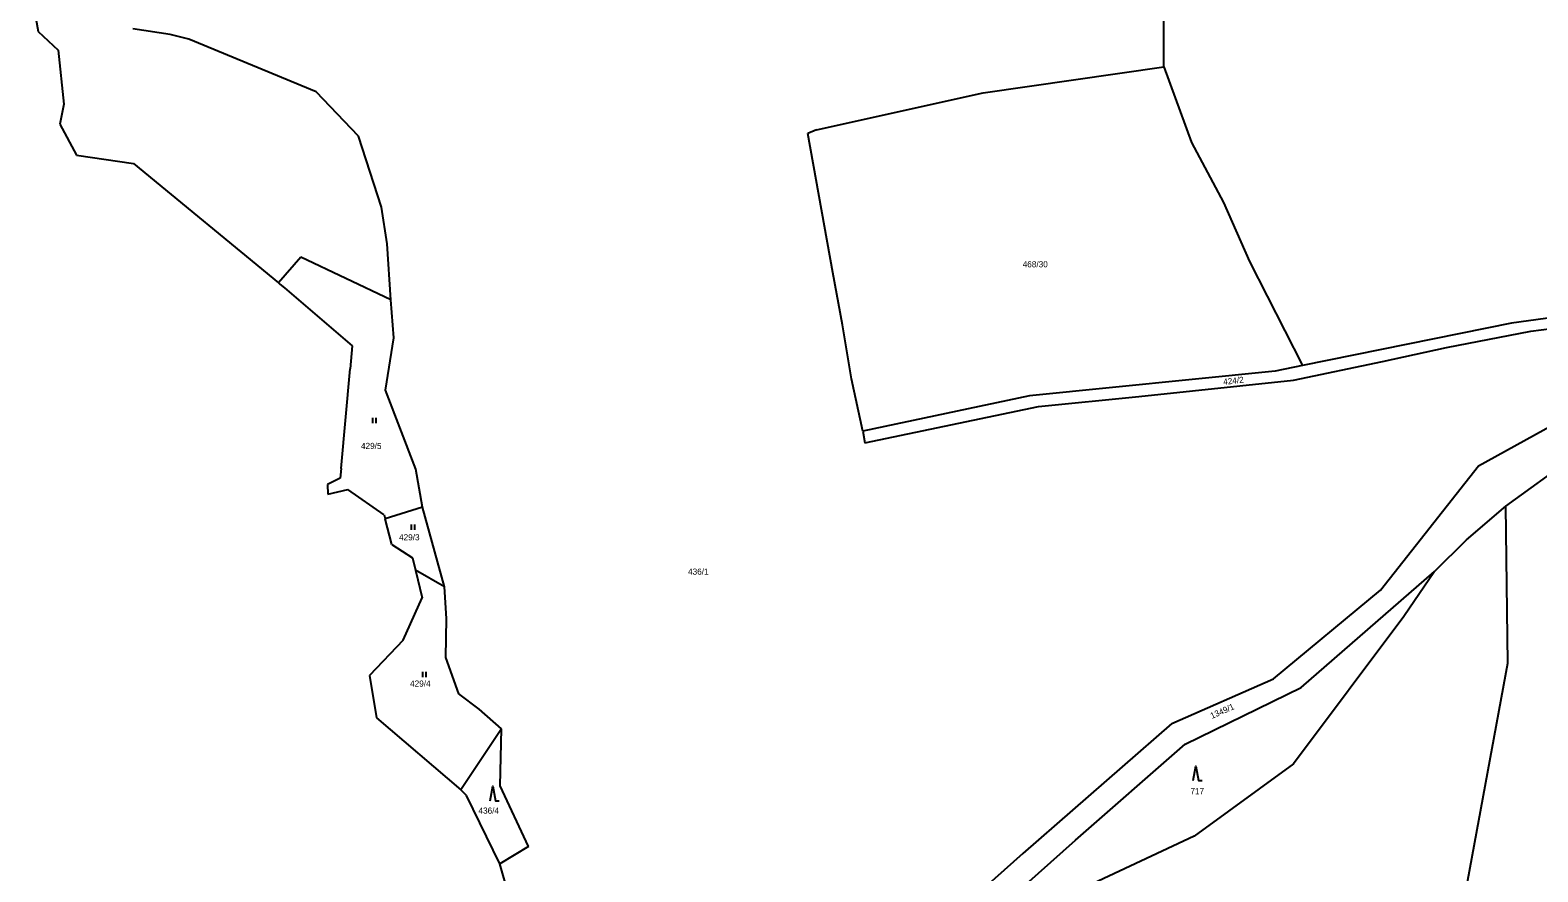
# Model space of a CAD drawing. Extents: x -852001 to -842497, y -1063614 to -1052182.
# Drawn here: x -845907.6 to -845490.2, y -1062182 to -1061949.1 of the extents above; entities that cross this region are included whole.
import ezdxf

# ---------------------------------------------------------------- set-up
doc = ezdxf.new("R2010")
doc.units = 0
for name, color, linetype in [('Default', 7, 'Continuous'), ('KN_HRANICE', 7, 'Continuous'), ('KN_KULTURY', 7, 'Continuous'), ('KN_PARCELY', 7, 'Continuous')]:
    doc.layers.add(name, color=color, linetype=linetype)

# ---------------------------------------------------------------- blocks, each defined once
blk = doc.blocks.new('306')
at = {"layer": 'Default'}
for p, q in [((-0.5, 1.5), (-0.5, 0)), ((0.5, 0), (0.5, 1.5))]:
    blk.add_line(p, q, dxfattribs=at)
blk = doc.blocks.new('308')
at = {"layer": 'Default'}
blk.add_lwpolyline([(-0.75, 0), (0, 4), (0.75, 0), (1.75, 0)], dxfattribs=at)

msp = doc.modelspace()

# ---------------------------------------------------------------- linework, layer by layer
at = {"layer": 'KN_HRANICE'}
for p, q in [((-845907.61, -1061936.84), (-845905.35, -1061949.46)), ((-845907.61, -1061936.84), (-845905.35, -1061949.46)), ((-845593.78, -1061959.19), (-845593.81, -1061940.64)), ((-845593.78, -1061959.19), (-845593.81, -1061940.64)), ((-845905.35, -1061949.46), (-845899.89, -1061954.64)), ((-845905.35, -1061949.46), (-845899.89, -1061954.64)), ((-845868.81, -1061950.29), (-845879.15, -1061948.69)), ((-845868.81, -1061950.29), (-845879.15, -1061948.69)), ((-845863.64, -1061951.61), (-845868.81, -1061950.29)), ((-845863.64, -1061951.61), (-845868.81, -1061950.29)), ((-845899.89, -1061954.64), (-845898.3, -1061969.58)), ((-845899.89, -1061954.64), (-845898.3, -1061969.58)), ((-845828.42, -1061966.16), (-845863.64, -1061951.61)), ((-845828.42, -1061966.16), (-845863.64, -1061951.61)), ((-845643.81, -1061966.46), (-845593.78, -1061959.19)), ((-845643.81, -1061966.46), (-845593.78, -1061959.19)), ((-845593.78, -1061959.19), (-845586.1, -1061980.16)), ((-845593.78, -1061959.19), (-845586.1, -1061980.16)), ((-845816.75, -1061978.37), (-845828.42, -1061966.16)), ((-845816.75, -1061978.37), (-845828.42, -1061966.16)), ((-845689.93, -1061976.66), (-845643.81, -1061966.46)), ((-845689.93, -1061976.66), (-845643.81, -1061966.46)), ((-845898.3, -1061969.58), (-845899.42, -1061975.13)), ((-845898.3, -1061969.58), (-845899.42, -1061975.13)), ((-845899.42, -1061975.13), (-845894.81, -1061983.7)), ((-845899.42, -1061975.13), (-845894.81, -1061983.7)), ((-845810.39, -1061998.09), (-845816.75, -1061978.37)), ((-845810.39, -1061998.09), (-845816.75, -1061978.37)), ((-845689.93, -1061976.66), (-845692.3, -1061977.63)), ((-845689.93, -1061976.66), (-845692.3, -1061977.63)), ((-845685.43, -1062016.18), (-845692.3, -1061977.63)), ((-845685.43, -1062016.18), (-845692.3, -1061977.63)), ((-845894.81, -1061983.7), (-845879, -1061985.97)), ((-845894.81, -1061983.7), (-845879, -1061985.97)), ((-845586.1, -1061980.16), (-845577.29, -1061996.8)), ((-845586.1, -1061980.16), (-845577.29, -1061996.8)), ((-845879, -1061985.97), (-845838.89, -1062019.01)), ((-845879, -1061985.97), (-845838.89, -1062019.01)), ((-845808.8, -1062008.17), (-845810.39, -1061998.09)), ((-845808.8, -1062008.17), (-845810.39, -1061998.09)), ((-845577.29, -1061996.8), (-845570.06, -1062013.09)), ((-845577.29, -1061996.8), (-845570.06, -1062013.09)), ((-845807.74, -1062023.68), (-845808.8, -1062008.17)), ((-845807.74, -1062023.68), (-845808.8, -1062008.17)), ((-845832.72, -1062011.87), (-845838.89, -1062019.01)), ((-845832.72, -1062011.87), (-845838.89, -1062019.01)), ((-845807.74, -1062023.68), (-845832.72, -1062011.87)), ((-845807.74, -1062023.68), (-845832.72, -1062011.87)), ((-845570.06, -1062013.09), (-845555.39, -1062041.89)), ((-845570.06, -1062013.09), (-845555.39, -1062041.89)), ((-845682.78, -1062030.58), (-845685.43, -1062016.18)), ((-845682.78, -1062030.58), (-845685.43, -1062016.18)), ((-845838.89, -1062019.01), (-845838.48, -1062019.35)), ((-845838.89, -1062019.01), (-845838.48, -1062019.35)), ((-845838.48, -1062019.35), (-845837.23, -1062020.38)), ((-845838.48, -1062019.35), (-845837.23, -1062020.38)), ((-845837.23, -1062020.38), (-845818.43, -1062036.47)), ((-845837.23, -1062020.38), (-845818.43, -1062036.47)), ((-845806.95, -1062034.24), (-845807.74, -1062023.68)), ((-845806.95, -1062034.24), (-845807.74, -1062023.68)), ((-845470.38, -1062026.35), (-845497.51, -1062030.16)), ((-845470.38, -1062026.35), (-845497.51, -1062030.16)), ((-845492.16, -1062032.41), (-845469.1, -1062029.34)), ((-845492.16, -1062032.41), (-845469.1, -1062029.34)), ((-845809.2, -1062048.66), (-845806.95, -1062034.24)), ((-845809.2, -1062048.66), (-845806.95, -1062034.24)), ((-845680.26, -1062045.53), (-845682.78, -1062030.58)), ((-845680.26, -1062045.53), (-845682.78, -1062030.58)), ((-845497.51, -1062030.16), (-845555.39, -1062041.89)), ((-845497.51, -1062030.16), (-845555.39, -1062041.89)), ((-845515.5, -1062036.89), (-845492.16, -1062032.41)), ((-845515.5, -1062036.89), (-845492.16, -1062032.41)), ((-845818.43, -1062036.47), (-845819.01, -1062042.76)), ((-845818.43, -1062036.47), (-845819.01, -1062042.76)), ((-845533.24, -1062040.8), (-845515.5, -1062036.89)), ((-845533.24, -1062040.8), (-845515.5, -1062036.89)), ((-845555.39, -1062041.89), (-845563, -1062043.43)), ((-845555.39, -1062041.89), (-845563, -1062043.43)), ((-845557.91, -1062045.95), (-845533.24, -1062040.8)), ((-845557.91, -1062045.95), (-845533.24, -1062040.8)), ((-845821.54, -1062070.34), (-845819.01, -1062042.76)), ((-845821.54, -1062070.34), (-845819.01, -1062042.76)), ((-845677.11, -1062060.07), (-845680.26, -1062045.53)), ((-845677.11, -1062060.07), (-845680.26, -1062045.53)), ((-845563, -1062043.43), (-845630.99, -1062050.28)), ((-845563, -1062043.43), (-845630.99, -1062050.28)), ((-845600.67, -1062050.42), (-845557.91, -1062045.95)), ((-845600.67, -1062050.42), (-845557.91, -1062045.95)), ((-845506.65, -1062069.62), (-845462.24, -1062045.1)), ((-845506.65, -1062069.62), (-845462.24, -1062045.1)), ((-845800.85, -1062070.54), (-845809.2, -1062048.66)), ((-845800.85, -1062070.54), (-845809.2, -1062048.66)), ((-845630.99, -1062050.28), (-845677.11, -1062060.07)), ((-845630.99, -1062050.28), (-845677.11, -1062060.07)), ((-845628.48, -1062053.22), (-845600.67, -1062050.42)), ((-845628.48, -1062053.22), (-845600.67, -1062050.42)), ((-845676.55, -1062063.28), (-845628.48, -1062053.22)), ((-845676.55, -1062063.28), (-845628.48, -1062053.22)), ((-845499.15, -1062080.77), (-845459.27, -1062051.94)), ((-845499.15, -1062080.77), (-845459.27, -1062051.94)), ((-845677.11, -1062060.07), (-845676.55, -1062063.28)), ((-845677.11, -1062060.07), (-845676.55, -1062063.28)), ((-845821.54, -1062070.34), (-845821.79, -1062073.02)), ((-845821.54, -1062070.34), (-845821.79, -1062073.02)), ((-845799, -1062081.12), (-845800.85, -1062070.54)), ((-845799, -1062081.12), (-845800.85, -1062070.54)), ((-845533.76, -1062104.01), (-845506.65, -1062069.62)), ((-845533.76, -1062104.01), (-845506.65, -1062069.62)), ((-845821.79, -1062073.02), (-845825.28, -1062074.82)), ((-845821.79, -1062073.02), (-845825.28, -1062074.82)), ((-845825.28, -1062074.82), (-845825.18, -1062077.51)), ((-845825.28, -1062074.82), (-845825.18, -1062077.51)), ((-845825.18, -1062077.51), (-845819.69, -1062076.21)), ((-845825.18, -1062077.51), (-845819.69, -1062076.21)), ((-845809.62, -1062083.2), (-845819.69, -1062076.21)), ((-845809.62, -1062083.2), (-845819.69, -1062076.21)), ((-845809.62, -1062083.2), (-845809.34, -1062084.29)), ((-845809.62, -1062083.2), (-845809.34, -1062084.29)), ((-845799, -1062081.12), (-845809.34, -1062084.29)), ((-845799, -1062081.12), (-845809.34, -1062084.29)), ((-845807.53, -1062091.38), (-845809.34, -1062084.29)), ((-845807.53, -1062091.38), (-845809.34, -1062084.29)), ((-845792.89, -1062103.14), (-845799, -1062081.12)), ((-845792.89, -1062103.14), (-845799, -1062081.12)), ((-845509.99, -1062090.09), (-845499.15, -1062080.77)), ((-845509.99, -1062090.09), (-845499.15, -1062080.77)), ((-845498.56, -1062124.27), (-845499.15, -1062080.77)), ((-845498.56, -1062124.27), (-845499.15, -1062080.77)), ((-845807.53, -1062091.38), (-845801.75, -1062095.07)), ((-845807.53, -1062091.38), (-845801.75, -1062095.07)), ((-845518.89, -1062098.85), (-845509.99, -1062090.09)), ((-845518.89, -1062098.85), (-845509.99, -1062090.09)), ((-845801.75, -1062095.07), (-845800.91, -1062098.53)), ((-845801.75, -1062095.07), (-845800.91, -1062098.53)), ((-845792.89, -1062103.14), (-845800.91, -1062098.53)), ((-845800.91, -1062098.53), (-845799.07, -1062106.19)), ((-845792.89, -1062103.14), (-845800.91, -1062098.53)), ((-845800.91, -1062098.53), (-845799.07, -1062106.19)), ((-845555.81, -1062130.94), (-845518.89, -1062098.85)), ((-845555.81, -1062130.94), (-845518.89, -1062098.85)), ((-845518.89, -1062098.85), (-845527.36, -1062111.38)), ((-845518.89, -1062098.85), (-845527.36, -1062111.38)), ((-845792.37, -1062111.89), (-845792.89, -1062103.14)), ((-845792.37, -1062111.89), (-845792.89, -1062103.14)), ((-845563.39, -1062128.62), (-845533.76, -1062104.01)), ((-845563.39, -1062128.62), (-845533.76, -1062104.01)), ((-845804.35, -1062117.86), (-845799.07, -1062106.19)), ((-845804.35, -1062117.86), (-845799.07, -1062106.19)), ((-845792.5, -1062122.7), (-845792.37, -1062111.89)), ((-845792.5, -1062122.7), (-845792.37, -1062111.89)), ((-845527.36, -1062111.38), (-845557.92, -1062152.14)), ((-845527.36, -1062111.38), (-845557.92, -1062152.14)), ((-845804.35, -1062117.86), (-845813.71, -1062127.7)), ((-845804.35, -1062117.86), (-845813.71, -1062127.7)), ((-845788.92, -1062132.78), (-845792.5, -1062122.7)), ((-845788.92, -1062132.78), (-845792.5, -1062122.7)), ((-845510.92, -1062191.27), (-845498.56, -1062124.27)), ((-845510.92, -1062191.27), (-845498.56, -1062124.27)), ((-845813.71, -1062127.7), (-845811.72, -1062139.37)), ((-845813.71, -1062127.7), (-845811.72, -1062139.37)), ((-845591.55, -1062140.98), (-845563.39, -1062128.62)), ((-845591.55, -1062140.98), (-845563.39, -1062128.62)), ((-845783.35, -1062137.02), (-845788.92, -1062132.78)), ((-845783.35, -1062137.02), (-845788.92, -1062132.78)), ((-845587.92, -1062146.66), (-845555.81, -1062130.94)), ((-845587.92, -1062146.66), (-845555.81, -1062130.94)), ((-845777.12, -1062142.46), (-845783.35, -1062137.02)), ((-845777.12, -1062142.46), (-845783.35, -1062137.02)), ((-845811.72, -1062139.37), (-845788.38, -1062159.34)), ((-845811.72, -1062139.37), (-845788.38, -1062159.34)), ((-845777.12, -1062142.46), (-845788.38, -1062159.34)), ((-845777.12, -1062142.46), (-845788.38, -1062159.34)), ((-845777.52, -1062158.24), (-845777.12, -1062142.46)), ((-845777.52, -1062158.24), (-845777.12, -1062142.46)), ((-845591.55, -1062140.98), (-845632.82, -1062176.92)), ((-845591.55, -1062140.98), (-845632.82, -1062176.92)), ((-845618.23, -1062173.22), (-845587.92, -1062146.66)), ((-845618.23, -1062173.22), (-845587.92, -1062146.66)), ((-845557.92, -1062152.14), (-845585.39, -1062172.12)), ((-845557.92, -1062152.14), (-845585.39, -1062172.12)), ((-845786.78, -1062160.85), (-845788.38, -1062159.34)), ((-845786.78, -1062160.85), (-845788.38, -1062159.34)), ((-845769.7, -1062174.95), (-845777.52, -1062158.24)), ((-845769.7, -1062174.95), (-845777.52, -1062158.24)), ((-845777.6, -1062179.8), (-845786.78, -1062160.85)), ((-845777.6, -1062179.8), (-845786.78, -1062160.85)), ((-845769.7, -1062174.95), (-845777.6, -1062179.8)), ((-845769.7, -1062174.95), (-845777.6, -1062179.8)), ((-845651.42, -1062202.77), (-845618.23, -1062173.22)), ((-845651.42, -1062202.77), (-845618.23, -1062173.22)), ((-845585.39, -1062172.12), (-845645.11, -1062200.07)), ((-845585.39, -1062172.12), (-845645.11, -1062200.07)), ((-845775.06, -1062188.48), (-845777.6, -1062179.8)), ((-845775.06, -1062188.48), (-845777.6, -1062179.8)), ((-845632.82, -1062176.92), (-845658.96, -1062200.15)), ((-845632.82, -1062176.92), (-845658.96, -1062200.15))]:
    msp.add_line(p, q, dxfattribs=at)

# ---------------------------------------------------------------- block references
at = {"layer": 'KN_KULTURY'}
for name, p in [('306', (-845812.31, -1062057.82)), ('306', (-845812.31, -1062057.82)), ('306', (-845801.66, -1062087.36)), ('306', (-845801.66, -1062087.36)), ('306', (-845798.5, -1062128.11)), ('306', (-845798.5, -1062128.11)), ('308', (-845584.93, -1062156.76)), ('308', (-845584.93, -1062156.76)), ('308', (-845779.54, -1062162.32)), ('308', (-845779.54, -1062162.32))]:
    msp.add_blockref(name, p, dxfattribs=at)

# ---------------------------------------------------------------- texts
at = {"layer": 'KN_PARCELY'}
for s, p in [('468/30', (-845632.86, -1062014.71)), ('468/30', (-845632.86, -1062014.71)), ('429/5', (-845816.03, -1062064.98)), ('429/5', (-845816.03, -1062064.98)), ('429/3', (-845805.5, -1062090.26)), ('429/3', (-845805.5, -1062090.26)), ('436/1', (-845725.49, -1062099.77)), ('436/1', (-845725.49, -1062099.77)), ('429/4', (-845802.44, -1062130.75)), ('429/4', (-845802.44, -1062130.75)), ('717', (-845586.42, -1062160.52)), ('717', (-845586.42, -1062160.52)), ('436/4', (-845783.5, -1062165.9)), ('436/4', (-845783.5, -1062165.9))]:
    msp.add_text(s, height=1.7, dxfattribs=at).set_placement(p)
for s, rotation, p in [('424/2', 6.474, (-845577.25, -1062047.26)), ('424/2', 6.474, (-845577.25, -1062047.26)), ('1349/1', 23.663, (-845580.47, -1062139.7)), ('1349/1', 23.663, (-845580.47, -1062139.7))]:
    msp.add_text(s, height=1.7, rotation=rotation, dxfattribs=at).set_placement(p)

doc.saveas('drawing.dxf')
